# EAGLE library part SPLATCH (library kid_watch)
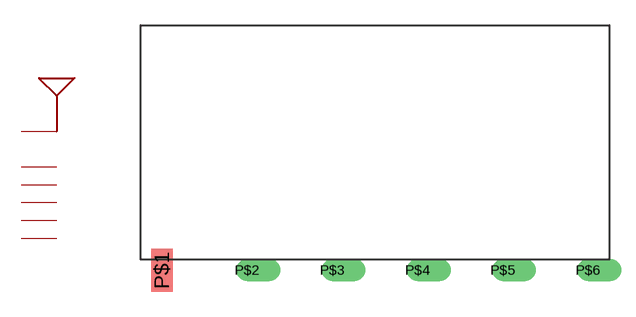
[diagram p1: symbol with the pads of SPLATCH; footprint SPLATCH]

Designator prefix -

## SPLATCH  [SPLATCH]
P$1  P$1
P$2  P$2
P$3  P$3
P$4  P$4
P$5  P$5
P$6  P$6

## Footprint SPLATCH (pad centres in mm)
smd 1.27 x 2.54: P$1 0,0
drill 0.813 offset: P$2 5.08,0; P$3 10.16,0; P$4 15.24,0; P$5 20.32,0; P$6 25.4,0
